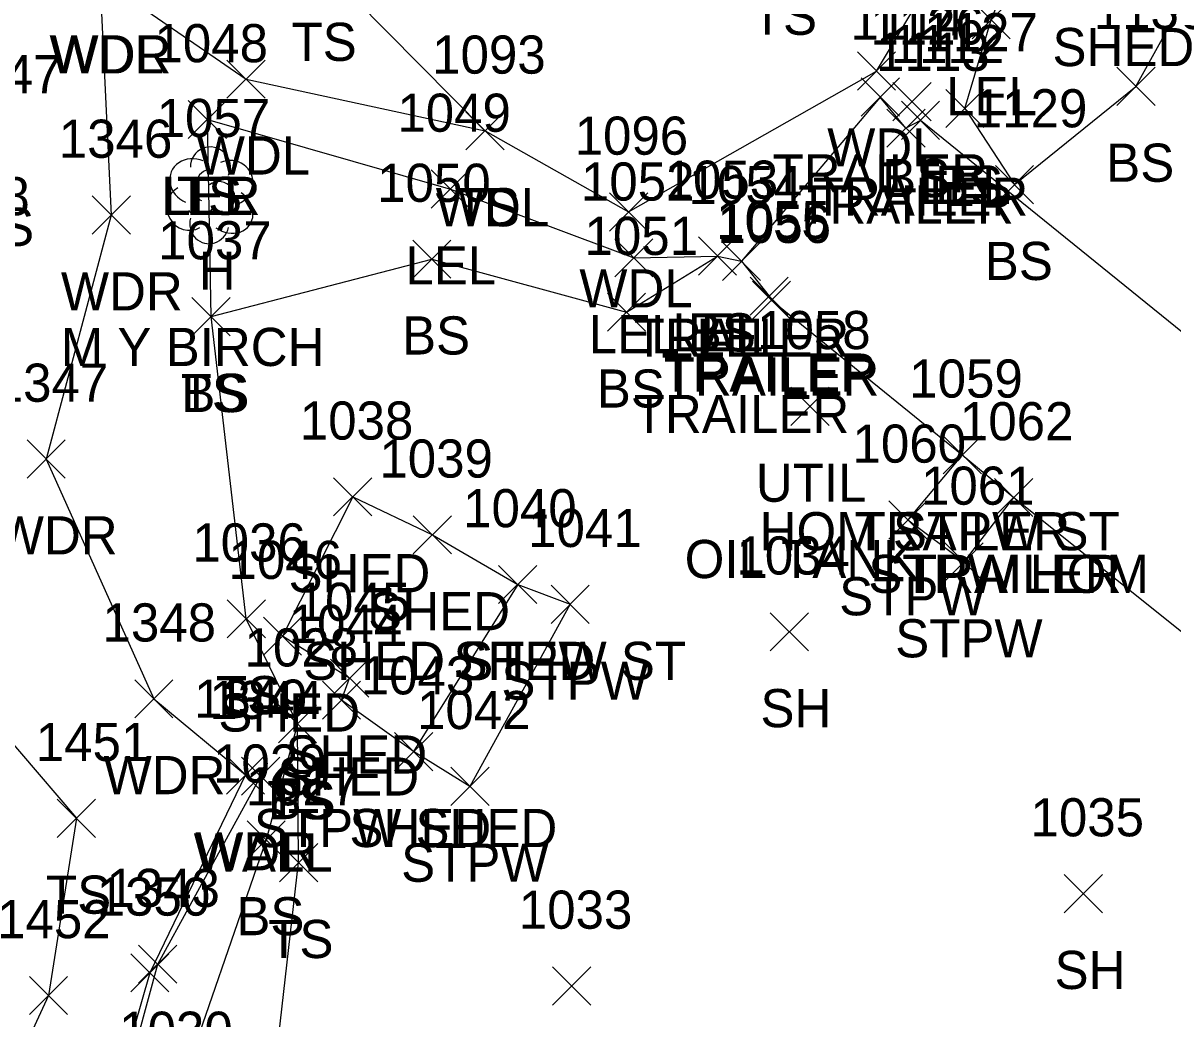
# Model space of a CAD drawing. Extents: x 1638344 to 1639591, y 610835 to 612202.
# Drawn here: x 1638740.9 to 1638801.1, y 611750.3 to 611802.5 of the extents above; entities that cross this region are included whole.
import ezdxf

# ---------------------------------------------------------------- set-up
doc = ezdxf.new("R2010")
doc.units = 0
for name, color, linetype in [('L_A', 7, 'Continuous'), ('L_C', 7, 'Continuous'), ('L_I', 7, 'Continuous'), ('L_TIC', 7, 'Continuous'), ('LARO', 7, 'Continuous'), ('LAWA', 7, 'Continuous'), ('LBC', 7, 'Continuous'), ('LBF', 7, 'Continuous'), ('LELB', 7, 'Continuous'), ('LTD', 7, 'Continuous'), ('LW', 7, 'Continuous'), ('U_A', 7, 'Continuous'), ('U_C', 7, 'Continuous'), ('U_I', 7, 'Continuous'), ('UDEFAULT', 7, 'Continuous')]:
    doc.layers.add(name, color=color, linetype=linetype)

msp = doc.modelspace()

# ---------------------------------------------------------------- linework, layer by layer
at = {"layer": 'L_TIC'}
for points in [[(1638790.619, 611801.629), (1638792.619, 611803.629)], [(1638792.619, 611801.629), (1638790.619, 611803.629)], [(1638784.61, 611798.942), (1638786.61, 611800.942)], [(1638786.61, 611798.942), (1638784.61, 611800.942)], [(1638751.572, 611798.518), (1638753.572, 611800.518)], [(1638753.572, 611798.518), (1638751.572, 611800.518)], [(1638798.206, 611798.14), (1638800.206, 611800.14)], [(1638800.206, 611798.14), (1638798.206, 611800.14)], [(1638784.81, 611797.58), (1638786.81, 611799.58)], [(1638786.81, 611797.58), (1638784.81, 611799.58)], [(1638786.466, 611797.334), (1638788.466, 611799.334)], [(1638788.466, 611797.334), (1638786.466, 611799.334)], [(1638789.238, 611796.979), (1638791.238, 611798.979)], [(1638791.238, 611796.979), (1638789.238, 611798.979)], [(1638789.238, 611796.979), (1638791.238, 611798.979)], [(1638791.238, 611796.979), (1638789.238, 611798.979)], [(1638749.545, 611796.403), (1638751.545, 611798.403)], [(1638751.545, 611796.403), (1638749.545, 611798.403)], [(1638749.545, 611796.403), (1638751.545, 611798.403)], [(1638751.545, 611796.403), (1638749.545, 611798.403)], [(1638749.545, 611796.403), (1638751.545, 611798.403)], [(1638751.545, 611796.403), (1638749.545, 611798.403)], [(1638786.915, 611796.359), (1638788.915, 611798.359)], [(1638788.915, 611796.359), (1638786.915, 611798.359)], [(1638764.098, 611795.806), (1638766.098, 611797.806)], [(1638766.098, 611795.806), (1638764.098, 611797.806)], [(1638764.098, 611795.806), (1638766.098, 611797.806)], [(1638766.098, 611795.806), (1638764.098, 611797.806)], [(1638786.153, 611795.949), (1638788.153, 611797.949)], [(1638788.153, 611795.949), (1638786.153, 611797.949)], [(1638762.281, 611792.759), (1638764.281, 611794.759)], [(1638764.281, 611792.759), (1638762.281, 611794.759)], [(1638791.844, 611792.992), (1638793.844, 611794.992)], [(1638793.844, 611792.992), (1638791.844, 611794.992)], [(1638744.509, 611791.396), (1638746.509, 611793.396)], [(1638746.509, 611791.396), (1638744.509, 611793.396)], [(1638744.509, 611791.396), (1638746.509, 611793.396)], [(1638746.509, 611791.396), (1638744.509, 611793.396)], [(1638771.619, 611791.558), (1638773.619, 611793.558)], [(1638773.619, 611791.558), (1638771.619, 611793.558)], [(1638761.304, 611789.087), (1638763.304, 611791.087)], [(1638763.304, 611789.087), (1638761.304, 611791.087)], [(1638771.893, 611789.153), (1638773.893, 611791.153)], [(1638773.893, 611789.153), (1638771.893, 611791.153)], [(1638776.279, 611789.25), (1638778.279, 611791.25)], [(1638778.279, 611789.25), (1638776.279, 611791.25)], [(1638776.279, 611789.25), (1638778.279, 611791.25)], [(1638778.279, 611789.25), (1638776.279, 611791.25)], [(1638777.535, 611788.972), (1638779.535, 611790.972)], [(1638779.535, 611788.972), (1638777.535, 611790.972)], [(1638777.535, 611788.972), (1638779.535, 611790.972)], [(1638779.535, 611788.972), (1638777.535, 611790.972)], [(1638778.981, 611787.141), (1638780.981, 611789.141)], [(1638780.981, 611787.141), (1638778.981, 611789.141)], [(1638779.108, 611786.933), (1638781.108, 611788.933)], [(1638781.108, 611786.933), (1638779.108, 611788.933)], [(1638749.738, 611786.073), (1638751.738, 611788.073)], [(1638751.738, 611786.073), (1638749.738, 611788.073)], [(1638749.738, 611786.073), (1638751.738, 611788.073)], [(1638751.738, 611786.073), (1638749.738, 611788.073)], [(1638771.513, 611786.304), (1638773.513, 611788.304)], [(1638773.513, 611786.304), (1638771.513, 611788.304)], [(1638789.106, 611778.828), (1638791.106, 611780.828)], [(1638791.106, 611778.828), (1638789.106, 611780.828)], [(1638789.106, 611778.828), (1638791.106, 611780.828)], [(1638791.106, 611778.828), (1638789.106, 611780.828)], [(1638741.095, 611778.611), (1638743.095, 611780.611)], [(1638743.095, 611778.611), (1638741.095, 611780.611)], [(1638757.16, 611776.627), (1638759.16, 611778.627)], [(1638759.16, 611776.627), (1638757.16, 611778.627)], [(1638757.16, 611776.627), (1638759.16, 611778.627)], [(1638759.16, 611776.627), (1638757.16, 611778.627)], [(1638791.8, 611776.592), (1638793.8, 611778.592)], [(1638793.8, 611776.592), (1638791.8, 611778.592)], [(1638791.8, 611776.592), (1638793.8, 611778.592)], [(1638793.8, 611776.592), (1638791.8, 611778.592)], [(1638786.259, 611775.419), (1638788.259, 611777.419)], [(1638788.259, 611775.419), (1638786.259, 611777.419)], [(1638761.338, 611774.636), (1638763.338, 611776.636)], [(1638763.338, 611774.636), (1638761.338, 611776.636)], [(1638789.197, 611773.215), (1638791.197, 611775.215)], [(1638791.197, 611773.215), (1638789.197, 611775.215)], [(1638765.806, 611772.034), (1638767.806, 611774.034)], [(1638767.806, 611772.034), (1638765.806, 611774.034)], [(1638765.806, 611772.034), (1638767.806, 611774.034)], [(1638767.806, 611772.034), (1638765.806, 611774.034)], [(1638768.558, 611770.999), (1638770.558, 611772.999)], [(1638770.558, 611770.999), (1638768.558, 611772.999)], [(1638751.583, 611770.238), (1638753.583, 611772.238)], [(1638753.583, 611770.238), (1638751.583, 611772.238)], [(1638753.481, 611769.326), (1638755.481, 611771.326)], [(1638755.481, 611769.326), (1638753.481, 611771.326)], [(1638753.481, 611769.326), (1638755.481, 611771.326)], [(1638755.481, 611769.326), (1638753.481, 611771.326)], [(1638780.041, 611769.556), (1638782.041, 611771.556)], [(1638782.041, 611769.556), (1638780.041, 611771.556)], [(1638756.998, 611767.126), (1638758.998, 611769.126)], [(1638758.998, 611767.126), (1638756.998, 611769.126)], [(1638746.744, 611766.046), (1638748.744, 611768.046)], [(1638748.744, 611766.046), (1638746.744, 611768.046)], [(1638756.578, 611765.975), (1638758.578, 611767.975)], [(1638758.578, 611765.975), (1638756.578, 611767.975)], [(1638754.265, 611764.736), (1638756.265, 611766.736)], [(1638756.265, 611764.736), (1638754.265, 611766.736)], [(1638754.265, 611764.736), (1638756.265, 611766.736)], [(1638756.265, 611764.736), (1638754.265, 611766.736)], [(1638760.353, 611763.274), (1638762.353, 611765.274)], [(1638762.353, 611763.274), (1638760.353, 611765.274)], [(1638760.353, 611763.274), (1638762.353, 611765.274)], [(1638762.353, 611763.274), (1638760.353, 611765.274)], [(1638751.548, 611762.054), (1638753.548, 611764.054)], [(1638753.548, 611762.054), (1638751.548, 611764.054)], [(1638752.342, 611761.986), (1638754.342, 611763.986)], [(1638754.342, 611761.986), (1638752.342, 611763.986)], [(1638763.305, 611761.455), (1638765.305, 611763.455)], [(1638765.305, 611761.455), (1638763.305, 611763.455)], [(1638742.68, 611759.781), (1638744.68, 611761.781)], [(1638744.68, 611759.781), (1638742.68, 611761.781)], [(1638752.623, 611758.653), (1638754.623, 611760.653)], [(1638754.623, 611758.653), (1638752.623, 611760.653)], [(1638754.327, 611757.457), (1638756.327, 611759.457)], [(1638756.327, 611757.457), (1638754.327, 611759.457)], [(1638795.452, 611755.836), (1638797.452, 611757.836)], [(1638797.452, 611755.836), (1638795.452, 611757.836)], [(1638746.527, 611751.68), (1638748.527, 611753.68)], [(1638748.527, 611751.68), (1638746.527, 611753.68)], [(1638746.944, 611752.134), (1638748.944, 611754.134)], [(1638748.944, 611752.134), (1638746.944, 611754.134)], [(1638768.637, 611750.994), (1638770.637, 611752.994)], [(1638770.637, 611750.994), (1638768.637, 611752.994)], [(1638741.219, 611750.498), (1638743.219, 611752.498)], [(1638743.219, 611750.498), (1638741.219, 611752.498)]]:
    msp.add_lwpolyline(points, dxfattribs=at)
at = {"layer": 'LARO'}
for points in [[(1638790.238, 611797.979), (1638791.619, 611802.629), (1638795.664, 611812.53), (1638804.38, 611820.545)], [(1638750.545, 611797.403), (1638763.281, 611793.759), (1638772.893, 611790.153), (1638777.279, 611790.25), (1638778.535, 611789.972)]]:
    msp.add_lwpolyline(points, dxfattribs=at)
at = {"layer": 'LAWA'}
for points in [[(1638744.908, 611804.817), (1638752.572, 611799.518), (1638765.098, 611796.806), (1638772.619, 611792.558), (1638785.61, 611799.942), (1638797.318, 611819.487)], [(1638744.908, 611804.817), (1638745.509, 611792.396)], [(1638745.509, 611792.396), (1638742.095, 611779.611), (1638747.744, 611767.046), (1638752.548, 611763.054), (1638747.527, 611752.68), (1638744.238, 611741.251), (1638742.049, 611729.716), (1638734.58, 611731.756), (1638732.677, 611730.845), (1638730.637, 611722.727)]]:
    msp.add_lwpolyline(points, dxfattribs=at)
at = {"layer": 'LBC'}
for points in [[(1638778.535, 611789.972), (1638779.981, 611788.141), (1638780.108, 611787.933), (1638790.106, 611779.828), (1638792.8, 611777.592), (1638809.966, 611763.882), (1638816.167, 611759.038), (1638824.136, 611752.467), (1638825.192, 611751.85), (1638832.585, 611761.2), (1638787.915, 611797.359), (1638787.153, 611796.949), (1638785.81, 611798.58)], [(1638785.81, 611798.58), (1638778.535, 611789.972)], [(1638758.16, 611777.627), (1638762.338, 611775.636), (1638766.806, 611773.034), (1638761.353, 611764.274), (1638757.578, 611766.975), (1638757.998, 611768.126), (1638754.481, 611770.326)], [(1638758.16, 611777.627), (1638754.481, 611770.326)]]:
    msp.add_lwpolyline(points, dxfattribs=at)
at = {"layer": 'LBF'}
for points in [[(1638790.106, 611779.828), (1638787.259, 611776.419), (1638790.197, 611774.215), (1638792.8, 611777.592)], [(1638766.806, 611773.034), (1638769.558, 611771.999), (1638764.305, 611762.455), (1638761.353, 611764.274)]]:
    msp.add_lwpolyline(points, dxfattribs=at)
at = {"layer": 'LELB'}
for points in [[(1638765.098, 611796.806), (1638756.545, 611805.474), (1638753.06, 611813.832), (1638756.773, 611824.489), (1638763.129, 611833.017), (1638785.599, 611828.575), (1638793.764, 611823.434), (1638780.667, 611806.841)], [(1638790.238, 611797.979), (1638792.844, 611793.992), (1638799.206, 611799.14), (1638802.616, 611805.312), (1638804.259, 611812.656)], [(1638738.449, 611722.448), (1638742.97, 611723.288), (1638747.892, 611726.858), (1638753.686, 611744.013), (1638755.327, 611758.457), (1638755.265, 611765.736), (1638752.583, 611771.238), (1638750.738, 611787.073), (1638750.545, 611797.403)], [(1638739.639, 611795.779), (1638737.982, 611789.384), (1638728.755, 611782.451), (1638734.71, 611771.274), (1638743.68, 611760.781), (1638742.219, 611751.498), (1638732.677, 611730.845)], [(1638750.738, 611787.073), (1638762.304, 611790.087), (1638772.513, 611787.304), (1638777.279, 611790.25)], [(1638755.265, 611765.736), (1638753.623, 611759.653), (1638748.785, 611745.649), (1638745.769, 611736.365)]]:
    msp.add_lwpolyline(points, dxfattribs=at)
at = {"layer": 'LTD'}
msp.add_line((1638750.657, 611793.485), (1638750.657, 611793.485), dxfattribs=at)
msp.add_line((1638750.657, 611793.485), (1638750.657, 611793.485), dxfattribs=at)
msp.add_arc((1638750.704, 611794.919), 1.047, 335.52715, 180.95627, dxfattribs=at)
for centre, major_axis, ratio, start_param, end_param in [((1638749.866, 611794.152), (1.21, -0.512), 0.895232, 1.570796, 4.712389), ((1638751.699, 611794.069), (-1.141, -0.483), 0.949671, 1.570796, 4.712389), ((1638750.449, 611793.944), (-0.208, -0.792), 0.645439, 3.141593, 6.283185), ((1638751.157, 611793.319), (-0.5, 0.667), 0.989748, 3.141593, 6.283185), ((1638749.574, 611792.777), (0.584, -1.042), 0.959034, 3.141593, 6.283185), ((1638751.658, 611792.652), (-1.09, 0.792), 0.841452, 1.570796, 4.712389), ((1638750.199, 611792.735), (-0.625, -0.083), 0.423636, 0, 3.141593), ((1638750.658, 611791.985), (0.265, 1.061), 0.942809, 1.570796, 4.712389)]:
    msp.add_ellipse(centre, major_axis=major_axis, ratio=ratio, start_param=start_param, end_param=end_param, dxfattribs=at)
at = {"layer": 'LW'}
msp.add_lwpolyline([(1638737.042, 611722.7), (1638738.904, 611727.28), (1638742.933, 611728.804), (1638744.205, 611739.391), (1638747.944, 611753.134), (1638753.342, 611762.986)], dxfattribs=at)
at = {"layer": 'UDEFAULT'}
for points in [[(1638781.124, 611781.37), (1638783.124, 611783.37)], [(1638783.124, 611781.37), (1638781.124, 611783.37)]]:
    msp.add_lwpolyline(points, dxfattribs=at)

# ---------------------------------------------------------------- texts
at = {"layer": 'L_A'}
for s, p in [('TS', (1638779.077, 611801.841)), ('TS', (1638754.954, 611800.474)), ('WDR', (1638742.27, 611799.817)), ('WDL', (1638742.325, 611799.817)), ('SHED', (1638794.831, 611800.201)), ('LEL', (1638789.256, 611797.629)), ('WDL', (1638749.99, 611794.518)), ('WDL', (1638783.027, 611794.942)), ('BS', (1638797.647, 611794.14)), ('TRAILER', (1638780.164, 611793.58)), ('BS', (1638785.907, 611793.334)), ('LEL', (1638787.875, 611792.979)), ('BS', (1638788.678, 611792.979)), ('LER', (1638748.128, 611792.403)), ('LEL', (1638748.183, 611792.403)), ('TS', (1638748.954, 611792.403)), ('TRAILER', (1638781.507, 611791.949)), ('TRAILER', (1638782.269, 611792.359)), ('WDL', (1638762.515, 611791.806)), ('TS', (1638763.507, 611791.806)), ('TS', (1638738.048, 611790.779)), ('BS', (1638791.285, 611788.992)), ('H', (1638750.09, 611788.485)), ('LEL', (1638760.919, 611788.759)), ('WDR', (1638742.871, 611787.396)), ('WDR', (1638742.871, 611787.396)), ('WDL', (1638770.036, 611787.558)), ('BS', (1638760.745, 611785.087)), ('LEL', (1638770.531, 611785.153)), ('TRAILER', (1638772.889, 611784.972)), ('LEL', (1638774.917, 611785.25)), ('BS', (1638775.72, 611785.25)), ('LEL', (1638776.173, 611784.972)), ('TRAILER', (1638774.336, 611783.141)), ('TRAILER', (1638774.463, 611782.933)), ('BS', (1638770.954, 611782.304)), ('TS', (1638749.148, 611782.073)), ('BS', (1638749.179, 611782.073)), ('WDR', (1638739.457, 611774.611)), ('HOM STPW ST', (1638779.484, 611774.828)), ('TRAILER', (1638784.46, 611774.828)), ('SHED', (1638754.798, 611772.627)), ('SHED', (1638754.798, 611772.627)), ('STPW HOM', (1638785.178, 611772.592)), ('TRAILER', (1638787.154, 611772.592)), ('STPW', (1638783.653, 611771.419)), ('SHED', (1638758.976, 611770.636)), ('STPW', (1638786.59, 611769.215)), ('SHED STPW ST', (1638755.57, 611768.034)), ('SHED', (1638763.444, 611768.034)), ('STPW', (1638765.952, 611766.999)), ('TS', (1638750.993, 611766.238)), ('SH', (1638779.529, 611765.556)), ('SHED', (1638751.119, 611765.326)), ('SHED', (1638751.119, 611765.326)), ('SHED', (1638754.636, 611763.126)), ('WDR', (1638745.106, 611762.046)), ('SHED', (1638754.216, 611761.975)), ('TS', (1638753.674, 611760.736)), ('BS', (1638753.706, 611760.736)), ('STPW SHED', (1638752.983, 611759.274)), ('SHED', (1638757.99, 611759.274)), ('WALL', (1638749.83, 611757.986)), ('WDR', (1638749.91, 611758.054)), ('STPW', (1638760.699, 611757.455)), ('TS', (1638742.09, 611755.781)), ('BS', (1638752.064, 611754.653)), ('TS', (1638753.736, 611753.457)), ('SH', (1638794.94, 611751.836))]:
    msp.add_text(s, height=2, dxfattribs=at).set_placement(p)
at = {"layer": 'L_C'}
for s, p in [('M Y BIRCH', (1638742.862, 611784.485)), ('TRAILER', (1638772.889, 611780.972))]:
    msp.add_text(s, height=2, dxfattribs=at).set_placement(p)
at = {"layer": 'L_I'}
for s, p in [('1130', (1638796.993, 611802.14)), ('1114', (1638784.251, 611801.58)), ('1126', (1638785.285, 611801.334)), ('1127', (1638788.112, 611800.979)), ('1127', (1638788.112, 611800.979)), ('1048', (1638747.773, 611800.403)), ('1048', (1638747.773, 611800.403)), ('1048', (1638747.773, 611800.403)), ('1112', (1638786.356, 611800.359)), ('1093', (1638762.326, 611799.806)), ('1093', (1638762.326, 611799.806)), ('1113', (1638785.594, 611799.949)), ('1447', (1638736.946, 611798.779)), ('1049', (1638760.501, 611796.759)), ('1129', (1638790.71, 611796.992)), ('1057', (1638747.886, 611796.485)), ('1096', (1638769.792, 611795.558)), ('1346', (1638742.761, 611795.396)), ('1346', (1638742.761, 611795.396)), ('1052', (1638770.121, 611793.153)), ('1053', (1638774.507, 611793.25)), ('1053', (1638774.507, 611793.25)), ('1050', (1638759.445, 611793.087)), ('1054', (1638775.763, 611792.972)), ('1054', (1638775.763, 611792.972)), ('1448', (1638735.289, 611792.384)), ('1055', (1638777.21, 611791.141)), ('1056', (1638777.282, 611790.933)), ('1051', (1638770.309, 611790.304)), ('1037', (1638747.967, 611790.073)), ('1037', (1638747.967, 611790.073)), ('1347', (1638739.402, 611782.611)), ('1059', (1638787.326, 611782.828)), ('1059', (1638787.326, 611782.828)), ('1038', (1638755.389, 611780.627)), ('1038', (1638755.389, 611780.627)), ('1062', (1638789.981, 611780.592)), ('1062', (1638789.981, 611780.592)), ('1060', (1638784.354, 611779.419)), ('1039', (1638759.559, 611778.636)), ('1061', (1638787.945, 611777.215)), ('1040', (1638763.948, 611776.034)), ('1040', (1638763.948, 611776.034)), ('1041', (1638767.354, 611774.999)), ('1036', (1638749.756, 611774.238)), ('1046', (1638751.654, 611773.326)), ('1046', (1638751.654, 611773.326)), ('1034', (1638778.269, 611773.556)), ('1045', (1638755.227, 611771.126)), ('1348', (1638745.051, 611770.046)), ('1044', (1638754.807, 611769.975)), ('1028', (1638752.493, 611768.736)), ('1028', (1638752.493, 611768.736)), ('1043', (1638758.581, 611767.274)), ('1043', (1638758.581, 611767.274)), ('1349', (1638749.847, 611766.054)), ('1344', (1638750.649, 611765.986)), ('1042', (1638761.533, 611765.455)), ('1451', (1638741.554, 611763.781)), ('1029', (1638750.844, 611762.653)), ('1027', (1638752.555, 611761.457)), ('1035', (1638793.68, 611759.836)), ('1343', (1638745.251, 611756.134)), ('1350', (1638744.747, 611755.68)), ('1033', (1638766.865, 611754.994)), ('1452', (1638739.527, 611754.498)), ('1030', (1638745.927, 611748.649))]:
    msp.add_text(s, height=2, dxfattribs=at).set_placement(p)
at = {"layer": 'U_A'}
msp.add_text('UTIL', height=2, dxfattribs=at).set_placement((1638779.289, 611777.37))
at = {"layer": 'U_C'}
msp.add_text('OIL TANK', height=2, dxfattribs=at).set_placement((1638775.557, 611773.37))
at = {"layer": 'U_I'}
msp.add_text('1058', height=2, dxfattribs=at).set_placement((1638779.352, 611785.37))

doc.saveas('drawing.dxf')
